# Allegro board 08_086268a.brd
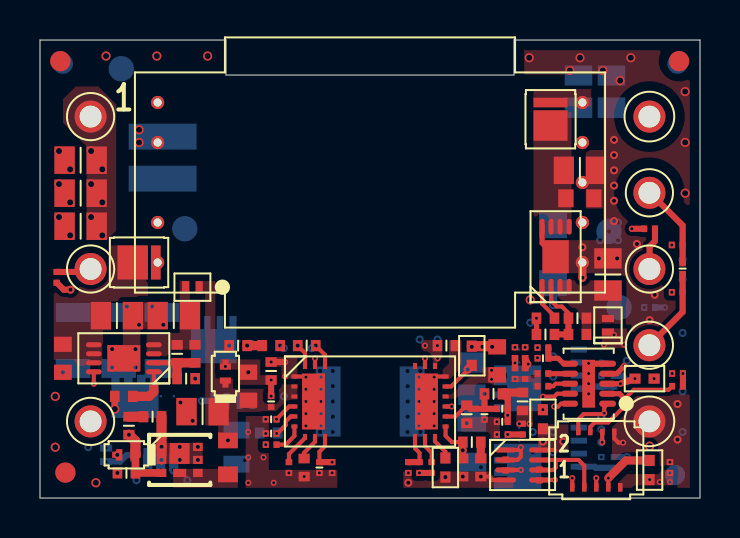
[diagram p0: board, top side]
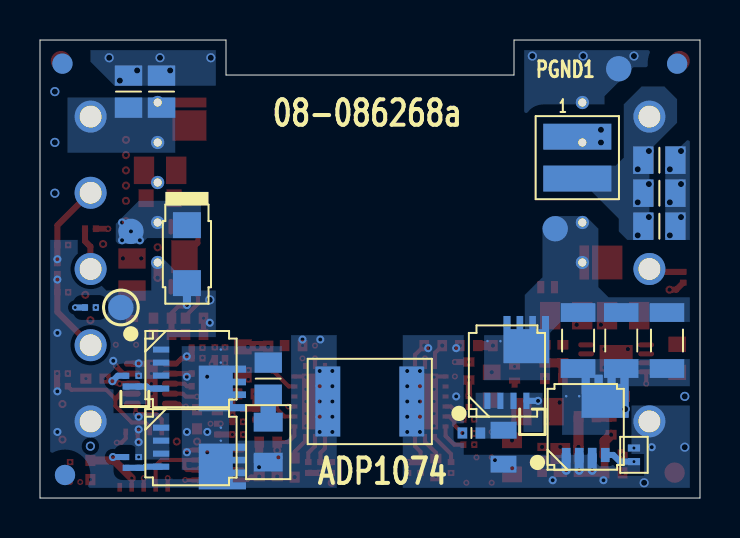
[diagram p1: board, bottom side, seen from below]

Outline 33 x 22.9 mm; copper layers: TOP, L2, L3, L4, L5, L6, L7, L8, L9, BOTTOM. Coordinates in mm from the lower left corner of the outline.
Outline path: 0,22.9 9.3,22.9 9.3,21.15 23.7,21.15 23.7,22.9 33,22.9 33,0 0,0 0,22.9

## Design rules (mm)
constraint set DEFAULT: min track width 0.305
net group DMAX: nets DMAX RT
net group ENABLE: nets ENABLE ON/OFFCONTROL
net group SR2: nets _N13 SR2
net group ASEL0: nets ALERT_N ASEL0 ASEL1 EN_I2C GP0 SCL SDA
net group COMP: nets _N50 COMP COMP_OUT
net group CS: nets CS
net group MODE: nets MODE PGOOD VREG2
net group PGATE: nets PGATE
net group PRI_AUX: nets _N29
net group SEC_AUX: nets _N31
net group SR_D: nets _N84
net group TRIM: nets _N4 FB FB_OUT IDAC OVP TRIM VSNS+ VSNS-

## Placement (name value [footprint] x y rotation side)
A1  ADA4075-2ACPZ  [DFN8_2X2]  24.13 1.65 270 top
C1  0.22UF  [C1206H71]  1.65 7.87 90 bottom
C2  0.22UF  [C1206H71]  3.94 7.87 90 bottom
C3  0.22UF  [C1206H71]  6.1 7.87 90 bottom
C4  2.2UF  [C0805H60]  26.92 20.32 90 bottom
C5  2.2UF  [C0805H60]  28.57 20.32 90 bottom
C6  2.2uF  [C0402H22]  30.23 5.97 180 top
C7  2.2uF  [C0402H22]  25.15 3.94 270 top
C8  2.2UF  [C0805H60]  2.03 15.24 180 bottom
C9  2.2UF  [C0805H60]  2.03 13.59 180 bottom
C10  2.2UF  [C0805H60]  8.13 4.32 180 top
C11  2.2UF  [C0805H60]  26.99 16.38 0 top
C12  1UF  [C0603]  26.99 14.99 0 top
C13  1UF  [C0603]  1.14 6.99 270 top
C14  2.2UF  [C0805H60]  3.85 9.12 0 top
C15  10NF  [C0402]  4.19 5.08 180 top
C16  10NF  [C0402]  25.27 8.99 180 top
C17  10UF  [C0805H55]  28.4 11.18 90 top
C18  2.2uF  [C0402H22]  30.48 1.4 90 top
C19  10UF  [C0805H55]  6.69 9.12 180 top
C20  2.2UF  [C0805H60]  2.03 15.24 180 top
C21  100NF  [C0402]  11.56 7.62 0 top
C22  1UF  [C0603]  22.86 6.86 270 top
C23  1UF  [C0603]  10.41 5.59 270 top
C24  0.015UF  [C0402]  13.21 1.52 270 top
C25  0.022uF  [C0402H22]  20.27 1.52 270 top
C26  0.033uF  [C0402]  22.04 1.52 270 top
C27  680pF  [C0402]  21.14 1.52 270 top
C28  2.2UF  [C0805H60]  2.03 13.59 180 top
C29  1000pF  [C0201]  13.97 1.52 270 top
C30  1000pF  [C0201]  11.56 3.94 180 top
C31  1000PF  [C0805H55]  21.59 5.97 270 bottom
C32  2.2uF  [C0402H22]  21.59 7.11 90 top
C34  0.1UF  [C0201]  11.56 4.83 90 top
C36  100PF  [C0201]  11.56 3.23 180 top
C39  10NF  [C0402]  26.87 8.18 0 top
C40  10NF  [C0402]  7.75 7.21 270 top
C41  100PF  [C0201]  23.11 3.81 180 top
C42  100PF  [C0201]  32.13 11.47 270 top
C45  2.2UF  [C0805H60]  2.03 16.89 180 bottom
C46  2.2UF  [C0805H60]  2.03 16.89 180 top
C47  100PF  [C0201]  22.23 4.19 270 top
C48  100PF  [C0201]  23.11 4.46 180 top
C49  2200pF  [C1812H63]  16.51 4.83 0 bottom
C63  100PF  [C0201]  25.15 6.99 180 top
D1  BZX884B11L-HG3-08  [DFN1006-2A]  9.27 6.22 90 top
D2  BZX884B11L-HG3-08  [DFN1006-2A]  4.32 2.16 180 top
D4  PMEG6010ESBYL  [DFN2_1X0_6]  3.3 2.16 270 bottom
D5  SDM1100LP-7  [DFN2020-2]  25.53 18.94 0 top
D6  V1F22-M3/H  [DO219AB]  25.65 12.19 270 bottom
D7  SDM1100LP-7  [DFN2020-2]  4.95 11.77 270 top
D13  PMEG6010ESBYL  [DFN2_1X0_6]  7.62 10.54 180 top
D15  PMEG6010ESBYL  [DFN2_1X0_6]  28.4 8.64 90 top
L1  1UH  [LSMSQ118H79_A]  6.13 17.02 90 bottom
NOREF  -  []  0 0 0 top
NOREF#2  -  []  -72.26 -74.17 0 top
NOREF#3  -  []  -228.6 -152.4 0 top
NOREF#4  -  [unnamed#2]  1.02 21.84 0 top
NOREF#5  -  []  -228.6 -152.4 0 top
NOREF#6  -  []  0 22.9 270 top
NOREF#7  -  []  325.12 314.96 0 top
NOREF#8  -  []  -228.6 -152.4 0 top
NOREF#9  -  []  0 0 0 top
NOREF#10  -  []  0 0 90 top
NOREF#11  -  [unnamed#2]  31.95 21.84 0 top
NOREF#12  -  []  0 0 0 top
NOREF#13  -  []  16.51 37.47 0 top
NOREF#14  -  []  33 0 90 top
NOREF#15  -  []  33 22.9 180 top
NOREF#16  -  [unnamed#2]  1.27 1.27 0 top
NOREF#17  -  [unnamed#2]  31.88 21.72 180 bottom
NOREF#18  -  [unnamed#2]  1.14 21.72 180 bottom
NOREF#19  -  [unnamed#2]  31.75 1.15 180 bottom
P1  5849-0-00-15-00-00-03-0  [CNMILMAX5849_AMH]  30.47 3.83 0 top
P2  3122-1-00-21-00-00-08-0  [CNMILLMAX3122-1]  2.53 19.07 0 top
P3  3122-1-00-21-00-00-08-0  [CNMILLMAX3122-1]  2.53 3.83 0 top
P4  3122-1-00-21-00-00-08-0  [CNMILLMAX3122-1]  2.53 11.45 0 top
P5  3122-1-00-21-00-00-08-0  [CNMILLMAX3122-1]  30.47 15.26 0 top
P6  3122-1-00-21-00-00-08-0  [CNMILLMAX3122-1]  30.47 11.45 0 top
P7  3122-1-00-21-00-00-08-0  [CNMILLMAX3122-1]  30.47 7.64 0 top
P8  5849-0-00-15-00-00-03-0  [CNMILMAX5849_AMH]  30.47 19.07 0 top
P10  AYF330935  [CNPANASONICAYF330935]  27.81 1.91 0 top
Q1  BSZ520N15NS3GATMA1  [TSDSON-8]  9.65 6.35 180 bottom
Q2  BSZ900N20NS3 G  [TSDSON-8]  25.45 6.45 270 bottom
Q3  BSZ900N20NS3 G  [TSDSON-8]  25.45 2.54 270 bottom
Q5  FDMC86259P  [POWER33]  5.71 3.56 180 bottom
Q6  FDMA86108LZ  [MLP6_2X2_PAD_9X1_PAD_2X_56]  6.99 1.91 270 top
R1  0  [R0201]  25.15 7.52 180 top
R2  0  [R0402]  20.32 7.62 180 top
R3  137K  [R0402]  22.68 5.21 180 top
R4  0  [R0201]  0.84 11.03 270 top
R5  2.8K  [R0402]  21.34 4.19 270 top
R6  220K  [R0402]  5.63 4.06 180 top
R7  220K  [R0402]  4.32 1.25 180 top
R8  220K  [R0402]  4.45 3.61 270 top
R9  0  [R0201]  23.28 1.65 90 top
R10  100  [R0603]  9.4 2.03 90 top
R11  2.05MEG  [R0402]  26.87 8.99 0 top
R12  124K  [R0402]  7.31 5.97 0 top
R13  0  [R0201]  24.26 7.26 90 top
R14  124K  [R0402]  25.27 8.18 180 top
R15  0  [R0201]  24.98 1.15 90 top
R17  10K  [R0402]  13.34 7.62 180 top
R18  4.7K  [R0402]  11.43 3.25 0 bottom
R20  3.74K  [R0402]  21.59 2.79 0 top
R21  0  [R0201]  28.7 5.84 90 bottom
R22  0  [R0402]  11.56 6.35 90 top
R23  0.005  [R0805]  9.82 2.54 270 bottom
R24  10K  [R0201]  28.07 5.84 90 bottom
R26  0  [R0201]  23.75 7.26 90 top
R27  0  [R0201]  12.45 1.52 270 top
R28  10K  [R0402]  9.91 7.62 180 top
R29  10  [R0805H20]  21.59 2.79 270 bottom
R30  0  [R0201]  18.41 1.52 270 top
R31  0  [R0201]  18.97 1.52 90 top
R32  8.2K  [R0201]  19.58 1.52 90 top
R37  20K  [R0201]  23.11 3.17 180 top
R38  2.05MEG  [R0402]  6.86 7.21 270 top
R39  10K  [R0201]  24.26 6.22 90 top
R40  10K  [R0201]  23.75 6.22 90 top
R41  0  [R0201]  31.86 12.65 0 top
R42  0  [R0201]  31.86 10.29 0 top
R43  0  [R0201]  30.48 13.46 180 top
R44  24K  [R0201]  11.56 2.67 0 top
R45  24K  [R0201]  14.61 1.52 270 top
R46  0  [R0201]  31.5 1.52 270 top
R48  0  [R0201]  28.7 1.78 90 bottom
R49  10K  [R0201]  28.07 1.78 90 bottom
R50  10  [R0402]  24.13 4.83 90 top
R51  1MEG  [R0201]  24.13 3.45 270 top
R64  10K  [R0201]  31.88 6.22 180 top
R65  10K  [R0201]  31.88 5.59 180 top
R66  10K  [R0201]  30.48 9.53 180 bottom
R69  10K  [R0201]  25.15 5.59 0 top
R70  10K  [R0201]  25.15 6.22 0 top
TP9  N/A  [TP_C127_P0]  28.96 9.53 180 bottom
TP10  N/A  [TP_C127_P0]  28.45 13.33 180 bottom
TP12  N/A  [TP_C127_P0]  7.24 13.46 180 bottom
TP16  N/A  [TP_C127_P0]  4.06 21.46 180 bottom
U4  EI14R1-0808-03-S03-20R-TH  [TTHL906W551H236]  5.88 19.77 0 top
U5  LT3062EDCB#PBF  [DFN8_2X3_PAD1_35X1_65_05-08-1718]  4.19 6.99 90 top
U6  LT3062EDCB#PBF  [DFN8_2X3_PAD1_35X1_65_05-08-1718]  25.78 12.06 0 top
U7  ADP1074ACCZ  [LGA24_4X8_2PAD2_8X1_15]  16.5 4.83 270 top
U9  LTC7106EDDB#PBF  [DFN10_3X2_PAD2_39X0_64]  27.43 5.71 90 top

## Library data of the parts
A1 = ADA4075_2: User Part Number: UPN; Tolerance: N/A; alternate symbols: (DFN8_2X2); tolerance: N/A
C1-C3 = CAP: Tolerance: 10; User Part Number: UPN; alternate symbols: (C1206H71L); tolerance: 10
C4 C5 C8-C11 C14 C17 C19 C20 C28 C45 C46 = CAP: User Part Number: UPN; Tolerance: 10; alternate symbols: (C0805L); tolerance: 10
C6 C7 C18 C32 = CAP: Tolerance: 20; User Part Number: UPN; alternate symbols: (C0402H22); tolerance: 20
C12 C13 C22 C23 = CAP: User Part Number: UPN; Tolerance: 10; alternate symbols: (C0603L); tolerance: 10
C15 C16 C21 C24 C26 C39 C40 = CAP: User Part Number: UPN; Tolerance: 10; alternate symbols: (C0402L); tolerance: 10
C25 = CAP: Tolerance: 10; User Part Number: UPN; alternate symbols: (C0402H22); tolerance: 10
C27 = CAP: User Part Number: UPN; Tolerance: 5; alternate symbols: (C0402L); tolerance: 5
C29 C30 = CAP: Tolerance: 10; User Part Number: UPN; alternate symbols: (C0201L); tolerance: 10
C31 = CAP: User Part Number: UPN; Tolerance: 5; alternate symbols: (C0805L); tolerance: 5
C34 = CAP: Tolerance: 20; User Part Number: UPN; alternate symbols: (C0201L); tolerance: 20
C36 C41 C42 C47 C48 C63 = CAP: Tolerance: 5; User Part Number: UPN; alternate symbols: (C0201L); tolerance: 5
C49 = CAP: Tolerance: 10; User Part Number: UPN; alternate symbols: (C1812H63); tolerance: 10
D1 D2 = DIOZNR: User Part Number: UPN; Tolerance: 2; alternate symbols: (DFN1006-2A); tolerance: 2
D4 D13 D15 = DIOSCHOTTKY: Tolerance: N/A; User Part Number: UPN; alternate symbols: (DFN2_1X0_6); tolerance: N/A
D5 D7 = DIOSCHOTTKY_V4: User Part Number: UPN; Tolerance: N/A; alternate symbols: (DFN2020-2); tolerance: N/A
D6 = DIOSCHOTTKY: User Part Number: UPN; Tolerance: N/A; alternate symbols: (DO219AB); tolerance: N/A
L1 = IND: User Part Number: UPN; Tolerance: 20; alternate symbols: (LSMSQ118H79_A); tolerance: 20
P1 P8 = CN1P: User Part Number: UPN; Tolerance: N/A; alternate symbols: (CNMILMAX5849_AMH); tolerance: N/A
P2-P7 = CN1P: User Part Number: UPN; Tolerance: N/A; alternate symbols: (CNMILLMAX3122-1); tolerance: N/A
P10 = CN9P: User Part Number: UPN; Tolerance: N/A; alternate symbols: (CNPANASONICAYF330935); tolerance: N/A
Q1 = TRANNMOSFET_V15: User Part Number: UPN; Tolerance: N/A; alternate symbols: (TSDSON-8); tolerance: N/A
Q2 Q3 = TRANNMOSFET8P: User Part Number: UPN; Tolerance: N/A; alternate symbols: (TSDSON-8); tolerance: N/A
Q5 = TRANPMOSFET_V9: Tolerance: N/A; User Part Number: UPN; alternate symbols: (POWER33); tolerance: N/A
Q6 = TRANNMOSFET_V31: Tolerance: N/A; User Part Number: UPN; alternate symbols: (MLP6_2X2_PAD_9X1_PAD_2X_56); tolerance: N/A
R1 R4 R9 R13 R15 R21 R26 R27 R30 R31 R41-R43 R46 R48 = RES: Tolerance: JUMPER; User Part Number: UPN; alternate symbols: (R0201L); tolerance: JUMPER
R2 R22 = RES: User Part Number: UPN; Tolerance: JUMPER; alternate symbols: (R0402L); tolerance: JUMPER
R3 = RES: User Part Number: UPN; Tolerance: 0.5; alternate symbols: (R0402L); tolerance: 0.5
R5 = RES: User Part Number: UPN; Tolerance: 0.1; alternate symbols: (R0402L); tolerance: 0.1
R6-R8 R11 R12 R14 R17 R18 R20 R28 R38 = RES: User Part Number: UPN; Tolerance: 1; alternate symbols: (R0402L); tolerance: 1
R10 = RES: User Part Number: UPN; Tolerance: 1; alternate symbols: (R0603); tolerance: 1
R23 = RES: User Part Number: UPN; Tolerance: 1; alternate symbols: (R0805L); tolerance: 1
R24 R39 R40 R49 R64-R66 R69 R70 = RES: Tolerance: 0.1; User Part Number: UPN; alternate symbols: (R0201L); tolerance: 0.1
R29 = RES: Tolerance: 0.1; User Part Number: UPN; alternate symbols: (R0805H20); tolerance: 0.1
R32 R44 R45 R51 = RES: Tolerance: 1; User Part Number: UPN; alternate symbols: (R0201L); tolerance: 1
R37 = RES: Tolerance: 5; User Part Number: UPN; alternate symbols: (R0201L); tolerance: 5
R50 = RES: User Part Number: UPN; Tolerance: 5; alternate symbols: (R0402L); tolerance: 5
TP9 TP10 TP12 TP16 = TP: alternate symbols: (TP_C127_P0)
U4 = XFMR9P_V4: User Part Number: UPN; Tolerance: N/A; alternate symbols: (TTHL906W551H236); tolerance: N/A
U5 U6 = ADLT3062: Tolerance: N/A; User Part Number: UPN; alternate symbols: (DFN8_2X3_PAD1_35X1_65_05-08-1718); tolerance: N/A
U7 = ADP1074: User Part Number: UPN; Tolerance: N/A; alternate symbols: (LGA24_4X8_2PAD2_8X1_15); tolerance: N/A
U9 = ADLTC7106_V2: User Part Number: UPN; Tolerance: N/A; alternate symbols: (DFN10_3X2_PAD2_39X0_64); tolerance: N/A

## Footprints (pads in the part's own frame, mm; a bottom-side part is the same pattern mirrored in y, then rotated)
C0201
  rect 0.305x0.33 smd: 1(-0.27,0) 2(0.27,0)
C0402
  rect 0.483x0.559 smd: 1(-0.45,0) 2(0.45,0)
C0402H22
  rect 0.559x0.508 smd: 1(-0.479,0) 2(0.479,0)
C0603
  rect 0.762x0.889 smd: 1(-0.7,0) 2(0.7,0)
C0805H55
  rect 1.016x1.372 smd: 1(-0.803,0) 2(0.803,0)
C0805H60
  rect 1.016x1.372 smd: 1(-0.803,0) 2(0.803,0)
C1206H71
  rect 0.94x1.727 smd: 1(-1.4,0) 2(1.4,0)
C1812H63
  rect 1.245x3.505 smd: 1(-2.1,0) 2(2.1,0)
CNMILLMAX3122-1
  round 1.6 hole 1.092: 1(0,0)
CNMILMAX5849_AMH
  round 1.6 hole 1.092: 1(0,0)
CNPANASONICAYF330935
  rect 0.229x0.432 smd: 1(-1.2,-1.369) 3(-0.6,-1.369) 5(0,-1.369) 7(0.6,-1.369) 9(1.2,-1.369)
  rect 0.229x0.33 smd: 2(-0.9,1.399) 4(-0.3,1.399) 6(0.3,1.399) 8(0.9,1.399)
DFN2_1X0_6
  rect 0.356x0.61 smd: A(0.34,0) C(-0.34,0)
DFN8_2X2
  oval 0.254x1.041 smd: 1(-0.75,-0.85) 2(-0.25,-0.85) 3(0.25,-0.85) 4(0.75,-0.85) 5(0.75,0.85) 6(0.25,0.85) 7(-0.25,0.85) 8(-0.75,0.85)
DFN8_2X3_PAD1_35X1_65_05-08-1718
  oval 0.254x0.787 smd: 1(-0.675,-1.5) 2(-0.225,-1.5) 3(0.225,-1.5) 4(0.675,-1.5) 5(0.675,1.5) 6(0.225,1.5) 7(-0.225,1.5) 8(-0.675,1.5)
  rect 1.321x1.651 smd: 9(0,0)
DFN10_3X2_PAD2_39X0_64
  oval 0.305x0.838 smd: 1(-1,-0.95) 2(-0.5,-0.95) 3(0,-0.95) 4(0.5,-0.95) 5(1,-0.95) 6(1,0.95) 7(0.5,0.95) 8(0,0.95) 9(-0.5,0.95) 10(-1,0.95)
  rect 2.388x0.635 smd: PAD(0,0)
DFN1006-2A
  custom 0.127x0.127 smd: A(0.454,0) C(-0.454,0)
DFN2020-2
  rect 1.702x1.524 smd: 1(0,-0.316)
  rect 1.702x0.483 smd: 2(0,0.837)
DO219AB
  rect 1.295x1.397 smd: A(1.45,0) C(-1.45,0)
LGA24_4X8_2PAD2_8X1_15
  rect 0.305x0.203 smd: 1(-1.775,-2.25) 2(-1.775,-2.75) 3(-1.775,-3.25) 10(1.775,-3.25) 11(1.775,-2.75) 12(1.775,-2.25) 13(1.775,2.25) 14(1.775,2.75) 15(1.775,3.25) 22(-1.775,3.25) 23(-1.775,2.75) 24(-1.775,2.25)
  rect 0.203x0.305 smd: 4(-1.25,-3.78) 5(-0.75,-3.78) 6(-0.25,-3.78) 7(0.25,-3.78) 8(0.75,-3.78) 9(1.25,-3.78) 16(1.25,3.78) 17(0.75,3.78) 18(0.25,3.78) 19(-0.25,3.78) 20(-0.75,3.78) 21(-1.25,3.78)
  rect 2.794x1.143 smd: PAD1(0,-2.825) PAD2(0,2.825)
LSMSQ118H79_A
  rect 1.295x3.404 smd: 1(-1.048,0) 2(1.048,0)
MLP6_2X2_PAD_9X1_PAD_2X_56
  rect 0.406x0.483 smd: 1(-0.65,-0.909) 2(0,-0.909) 3(0.65,-0.909) 4(0.65,0.909) 5(0,0.909) 6(-0.65,0.909)
  rect 1.041x0.991 smd: PAD1(-0.321,0)
  rect 0.406x0.66 smd: PAD2(0.653,0)
POWER33
  rect 0.432x0.711 smd: 1(-0.975,-1.404) 2(-0.325,-1.404) 3(0.325,-1.404) 4(0.975,-1.404)
  custom 0.54x0.54 smd: 5(0.97,1.531)
  round 0.127 smd: 6(0.325,1.535) 7(-0.325,1.535) 8(-0.975,1.535)
R0201
  rect 0.305x0.33 smd: 1(-0.27,0) 2(0.27,0)
R0402
  rect 0.483x0.559 smd: 1(-0.45,0) 2(0.45,0)
R0603
  rect 0.787x0.991 smd: 1(-0.85,0) 2(0.85,0)
R0805
  rect 0.838x1.295 smd: 1(-0.85,0) 2(0.85,0)
R0805H20
  rect 0.94x1.448 smd: 1(-1,0) 2(1,0)
TP_C127_P0
  round 1.27 smd: 1(0,0)
TSDSON-8
  rect 0.305x0.813 smd: 1(-0.975,-1.494) 2(-0.325,-1.494) 3(0.325,-1.494) 4(0.975,-1.494)
  custom 0.572x0.572 smd: 5(0.965,1.57)
  round 0.127 smd: 6(0.325,1.494) 7(-0.325,1.494) 8(-0.975,1.494)
TTHL906W551H236
  round 0.66 hole 0.406: 1(0,0) 2(0,-2) 4(0,-6) 5(0,-8) 6(21.238,-8) 7(21.238,-6) 8(21.238,-4) 9(21.238,-2) 10(21.238,0)
unnamed#2
  round 1.016 smd: (0,0)

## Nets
3V3_EXT: C6.2(N2) C18.2(N2) P10.7 R39.1 R40.1 R64.1 R65.1 R66.1 R69.1 R70.1 U9.3(VDD)
AGND1: C24.2(N2) C29.2(N2) C30.2(N2) C36.2(N2) R22.2(N2) R27.2(N2) R45.2(N2) U7.4 U7.PAD1
AGND2: A1.4(V-) C7.1 C25.2(N2) C26.2(N2) C27.2(N2) C41.2(N2) C47.2(N2) P10.1 R2.1 R5.2(N2) R30.2(N2) R37.2(N2) R42.1 U7.21 U7.PAD2
DGND: C6.1 C18.1 C63.2(N2) P10.9(N9) R13.2(N2) R26.2(N2) R46.2(N2) U9.5 U9.PAD
PGND1: C8.2(N2) C9.2(N2) C10.2(N2) C13.2(N2) C14.2(N2) C15.2(N2) C19.2(N2) C20.2(N2) C23.1 C28.2(N2) C34.2(N2) C45.2(N2) C46.2(N2) C49.1 D1.A(P) D2.A(P) D4.C P3.1(N1) Q5.1 Q5.2 Q5.3(S3) R12.2(N2) R17.2(N2) R22.1 R23.2(N2) R28.2(N2) TP16.1(TP1) U4.1 U5.8 U5.9 U7.3
PGND2: C4.2(N2) C5.2(N2) C11.2(N2) C12.2(N2) C16.2(N2) C17.2(N2) C22.1 C32.2(N2) C49.2(N2) D6.A(P) P1.1(N1) P10.8 Q2.1 Q2.2 Q2.3(S3) Q3.1 Q3.2 Q3.3(S3) R2.2(N2) R14.2(N2) R24.2(N2) R29.2(N2) R46.1 R49.2(N2) TP9.1(TP1) U4.6 U6.8 U6.9 U7.22
VIN+: C8.1 C9.1 C20.1 C28.1 C45.1 C46.1 L1.1 P2.1(N1) Q6.1 Q6.2 Q6.5 Q6.6 Q6.PAD1 R6.1
VIN_IC_1: C10.1 C23.2(N2) C34.1 D1.C D13.C R7.2(N2) R10.2(N2) U7.5 U7.6
VIN_IC_2: A1.8 C7.2(N2) C22.2(N2) D15.C U7.19
_N2: Q1.1 Q1.2 Q1.3(S3) R18.1 R23.1
_N3: C1.1 C2.1 C3.1 Q5.5 Q5.6 Q5.7 Q5.8
_N4: C41.1 C48.1 R3.1 R41.1 R50.2(N2)
_N8: R6.2(N2) R8.1
_N13: Q3.4 R48.1 R49.1
_N19: D2.C Q6.3 R7.1 R8.2(N2)
_N21: Q6.4 Q6.PAD2(S2) R10.1
_N27: C13.1 C14.1 D7.1(C) U5.5 U5.6 U5.7(SHDN_N)
_N29: C40.2(N2) R12.1 R38.2(N2) U5.2
_N31: C39.1 R11.1 R14.1 U6.2
_N33: C11.1 C12.1 D5.1(C) U6.5 U6.6 U6.7(SHDN_N)
_N36: C16.1 U6.1
_N37: C15.1 U5.1
_N50: C26.1 R20.2(N2)
_N52: Q2.4 R21.1 R24.1
_N59: C21.1 D4.A(P) Q5.4 R28.1
_N83: L1.2(N2) U4.2
_N84: C31.2(N2) R29.1
_N125: D5.2 U4.10
_N128: D7.2 U4.5
_N133: C1.2(N2) C2.2(N2) C3.2(N2) Q1.5 Q1.6 Q1.7 Q1.8 TP12.1(TP1) U4.4
ALERT_N: P10.6 R66.2(N2) U9.4
ASEL0: R26.1 R40.2(N2) U9.9
ASEL1: R13.1 R39.2(N2) U9.10
COMP: A1.3 C27.1 R9.1 R20.1 U7.16
COMP_OUT: A1.1 A1.2 P10.5 R9.2(N2)
CS: C36.1 R18.2(N2) U7.8
DMAX: C29.1 R44.1 R45.1 U7.12
EN_I2C: R70.2(N2) U9.7
ENABLE: C30.1 R4.2(N2) U7.7
FB: A1.5 C47.1 C48.2(N2) R1.2(N2) R3.2(N2) R5.1 R15.1 R43.2(N2) U7.17
FB_OUT: A1.6 A1.7 P10.3 R15.2(N2)
GP0: R69.2(N2) U9.8
IDAC: C63.1 R1.1 U9.6
MODE: R30.1 R31.2(N2) U7.13
NGATE: Q1.4 R17.1 U7.1
ON/OFFCONTROL: P4.1(N1) R4.1
OVP: R37.1 R51.2(N2) U7.18
PGATE: C21.2(N2) U7.2
PGOOD: R32.2(N2) U7.14
PRI_AUX: C19.1 C40.1 D13.A(P) R38.1 U5.3 U5.4
RT: R44.2(N2) U7.9
SCL: P10.4 R65.2(N2) U9.2
SDA: P10.2 R64.2(N2) U9.1
SEC_AUX: C17.1 C39.2(N2) D15.A(P) R11.2(N2) U6.3 U6.4
SR1: U7.24
SR2: R21.2(N2) R48.2(N2) U7.23
SR_D: C31.1 D6.C Q2.5 Q2.6 Q2.7 Q2.8 Q3.5 Q3.6 Q3.7 Q3.8 TP10.1(TP1) U4.7 U4.8(NC)
SS1: C24.1 U7.11
SS2: C25.1 U7.15
SYNC: R27.1 U7.10
TRIM: P6.1(N1) R43.1
VOUT: C4.1 C5.1 P8.1(N1) R50.1 R51.1 U4.9
VREG2: C32.1 R31.1 R32.1 U7.20(VREG2)
VSNS+: C42.1 P5.1(N1) R41.2(N2)
VSNS-: C42.2(N2) P7.1(N1) R42.2(N2)

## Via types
v1: diameter 0.305, hole 0.152, TOP to L2, 100 vias
v2: diameter 0.305, hole 0.152, L2 to L3, 97 vias
v3: diameter 0.762, hole 0.406, L3 to L8, 13 vias
v4: diameter 0.457, hole 0.305, L3 to L8, 39 vias
v5: diameter 0.406, hole 0.203, L8 to L9, 63 vias
v6: diameter 0.305, hole 0.152, L9 to BOTTOM, 6 vias
v7: diameter 0.305, hole 0.152, L4 to L5, 3 vias
v8: diameter 0.305, hole 0.152, L8 to L9, 9 vias
v9: diameter 0.406, hole 0.203, L9 to BOTTOM, 62 vias
v10: diameter 0.457, hole 0.305, TOP to BOTTOM, 32 vias
v11: diameter 0.66, hole 0.406, L2 to L3, 2 vias
v12: diameter 0.66, hole 0.406, L3 to L8, 6 vias
v13: diameter 0.457, hole 0.305, L6 to L7, 1 via
v14: diameter 0.66, hole 0.406, L8 to L9, 1 via
v15: diameter 0.406, hole 0.203, TOP to L2, 57 vias
v16: diameter 0.406, hole 0.203, L2 to L3, 50 vias
v17: diameter 0.305, hole 0.152, L6 to L7, 3 vias
v18: diameter 0.457, hole 0.305, L2 to L3, 1 via

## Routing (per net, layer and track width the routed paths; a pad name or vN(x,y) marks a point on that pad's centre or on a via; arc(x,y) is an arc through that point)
3V3_EXT: length 35.2
  TOP w0.203: P10.7 v2(28.41,0.99)
  TOP w0.254: U9.3 v2(29.02,5.71)
  TOP w0.305: R65.1 v2(32.15,6.22) ; v2(29.02,5.71) v2(29.75,5.97)
  TOP w0.406: C18.2 29.3,1.88 v2(28.41,0.99)
  L3 w0.305: v3(31.75,6.99) 32.15,6.59 v2(32.15,6.22) ; v2(23.75,5.95) v4(23.38,5.95)
  L3 w0.406: v3(28.82,0.99) v2(28.41,0.99) ; v3(31.75,6.99) 31.58,6.99 30.96,6.36 30.14,6.36 v2(29.75,5.97) v2(29.02,5.71)
  L6 w0.406: v4(23.38,5.95) 21.97,4.54 21.97,3.3 22.48,2.79 24.51,2.79 25.65,3.94 27.94,3.94 29.33,2.55 29.33,1.5 v3(28.82,0.99) 30.2,0.99 32.29,3.08 32.29,5.05 31.75,5.59 v3(31.75,6.99) 31.75,8.23 31.62,8.36 v3(31.62,9.14)
  L8 w0.406: v3(31.62,9.14) v6(31.24,9.53)
  BOTTOM w0.305: R66.1 v6(31.24,9.53)
AGND1: length 1.3
  TOP w0.203: U7.4 13.26,6.08 v2(13.29,6.05)
  TOP w0.305: v2(12.26,6.8) v2(11.56,6.8)
  vias: v1(10.41,3.3) v1(10.41,2.03) v1(10.41,0.76) v1(11.18,2.03) v1(11.29,3.94) v1(11.29,3.23) v1(11.68,0.76) v1(12.26,6.08) v1(12.45,1.25) v1(13.21,1.07) v1(13.29,5.44) v1(13.29,4.83) v1(13.29,4.22) v1(13.29,3.61) v1(13.97,1.25) v1(14.06,6.05) v1(14.06,5.44) v1(14.06,4.83) v1(14.06,4.22) v1(14.06,3.61) v1(14.61,1.25) v2(10.41,3.3) v2(10.41,2.03) v2(10.41,0.76) v2(11.18,2.03) v2(11.29,3.23) v2(11.68,0.76) v2(12.26,6.08) v2(12.45,1.25) v2(13.21,1.07) v2(13.29,5.44) v2(13.29,4.83) v2(13.29,4.22) v2(13.29,3.61) v2(13.97,1.25) v2(14.06,6.05) v2(14.06,5.44) v2(14.06,4.83) v2(14.06,4.22) v2(14.06,3.61) v2(14.61,1.25)
AGND2: length 14.9
  TOP w0.203: v1(19.71,6.05) 19.74,6.08 U7.21 ; v16(22.04,1.07) 22.45,1.07 22.62,0.9 A1.4 ; P10.1 v2(26.61,0.99)
  L3 w0.305: v2(31.59,10.29) v4(31.95,10.29)
  L6 w0.305: v4(31.95,10.29) 31.14,9.73 29.41,9.73 24.13,4.45 24.13,3.94 23.7,3.51 v4(22.84,3.51)
  vias: v1(18.41,1.25) v1(18.94,6.05) v1(18.94,5.44) v1(18.94,4.83) v1(18.94,4.22) v1(18.94,3.61) v1(19.71,5.44) v1(19.71,4.83) v1(19.71,4.22) v1(19.71,3.61) v1(22.23,3.92) v1(22.84,3.81) v1(22.84,3.17) v1(25.15,4.42) v2(18.94,6.05) v2(18.94,5.44) v2(18.94,4.83) v2(18.94,4.22) v2(18.94,3.61) v2(22.23,3.92) v2(22.84,3.81) v2(25.15,4.42) v15(18.41,0.76) v15(20.27,1.04) v15(21.14,1.07) v15(21.34,3.74) v16(18.41,0.76) v16(20.27,1.04) v16(21.14,1.07) v16(21.34,3.74)
DGND: length 2
  TOP w0.305: U9.5 27.43,6.71 v2(27.43,6.22) v2(27.43,5.71)
  vias: v1(23.75,7.53) v1(24.26,7.53) v1(24.88,7.01) v1(27.43,6.73) v1(27.43,5.21) v1(30.48,0.92) v1(30.71,5.97) v1(30.99,0.8) v1(31.5,1.25) v1(31.5,0.8) v2(23.75,7.53) v2(24.26,7.53) v2(24.88,7.01) v2(27.43,6.73) v2(27.43,5.21) v2(30.48,0.92) v2(30.99,0.8) v2(31.5,1.25) v2(31.5,0.8) v10(30.48,2.59)
PGND1: length 19.7
  TOP w0.203: U5.8 v2(2.69,5.71) ; U7.3 13.25,7.26 v16(12.88,7.62)
  TOP w0.305: C15.2 v10(3.74,4.45) ; v2(11.56,5.1) v2(11.56,5.9)
  L2 w0.762: v18(5.52,16.75) 4.2,16.75
  L2 w1.016: U4.1 4.57,19.77
  L3 w0.457: v18(5.52,16.75) v12(4.86,16.75)
  L3 w0.762: 4.45,20.32 4.99,19.77 U4.1
  L4 w1.016: U4.1 4.48,19.77
  L5 w1.016: U4.1 4.61,19.77
  L6 w0.66: v12(4.86,16.75) 5.46,16.75 ; U4.1 4.27,19.77
  L7 w0.66: U4.1 4.36,19.77
  L8 w1.016: U4.1 4.48,19.77
  L9 w0.66: U4.1 4.48,19.77
  BOTTOM w0.457: Q5.3 v9(5.39,1.39) ; Q5.2 v9(6.04,1.39) ; Q5.1 v9(6.69,1.39)
  vias: v1(9.27,6.58) v2(9.27,6.58) v2(10.41,6.29) v3(1.02,21.59) v4(0.76,0.89) v4(0.89,7.87) v4(1.61,9.14) v4(3.17,9.91) v4(4.19,6.99) v4(4.57,15.88) v4(4.57,13.21) v4(5.08,5.71) v4(5.08,3.81) v4(8.51,9.53) v4(8.76,2.41) v4(9.65,1.27) v4(11.56,5.5) v4(12.9,8.17) v4(14.27,0.74) v4(14.64,5.97) v4(14.64,4.45) v4(14.64,2.92) v5(2.41,2.54) v5(4.83,0.89) v5(7.37,0.89) v5(9.39,1.49) v5(10.25,1.89) v5(12.19,7.49) v5(12.19,5.08) v5(13.59,7.49) v5(14,6.35) v5(14,5.59) v5(14,4.83) v5(14,4.06) v5(14,3.3) v5(14.64,6.35) v5(14.64,5.59) v5(14.64,4.83) v5(14.64,4.06) v5(14.64,3.3) v6(3.3,2.5) v8(3.3,2.5) v9(2.41,2.54) v9(4.83,0.89) v9(7.37,0.89) v9(9.39,1.49) v9(10.25,1.89) v9(12.19,7.49) v9(12.19,5.08) v9(13.59,7.49) v9(14,6.35) v9(14,5.59) v9(14,4.83) v9(14,4.06) v9(14,3.3) v9(14.64,6.35) v9(14.64,5.59) v9(14.64,4.83) v9(14.64,4.06) v9(14.64,3.3) v10(0.76,5.08) v10(0.76,2.54) v10(0.95,17.35) v10(0.95,15.7) v10(0.95,14.05) v10(1.51,16.43) v10(1.51,14.78) v10(1.51,13.13) v10(2.79,0.76) v10(3.3,22.1) v10(5.84,22.1) v10(8.38,22.1) v15(1.14,6.29) v15(3.61,7.44) v15(3.61,6.53) v15(3.86,2.16) v15(4.34,9.58) v15(4.78,7.44) v15(4.78,6.53) v15(4.95,8.66) v15(5.61,9.58) v15(6.17,8.66) v15(7.02,4.78) v15(7.63,3.86) v15(7.76,5.97) v15(9.46,7.62) v15(10.41,6.29) v16(1.14,6.29) v16(3.61,7.44) v16(3.61,6.53) v16(3.86,2.16) v16(4.78,7.44) v16(4.78,6.53) v16(5.61,9.58) v16(6.17,8.66) v16(7.02,4.78) v16(7.63,3.86) v16(9.46,7.62)
PGND2: length 22.3
  TOP w0.203: v2(29.16,2.77) 28.92,2.77 28.71,2.98 P10.8
  TOP w0.254: R14.2 v2(24.82,8.99) ; U6.8 25.11,12.74 U6.9
  TOP w0.305: C32.2 v16(21.59,7.56)
  TOP w0.406: v15(27.12,11.01) U4.6
  TOP w0.508: C32.2 22.86,7.59 C22.1
  L2 w0.66: v2(28.85,11.98) v2(27.94,11.98) 27.74,11.77 U4.6
  L3 w0.406: v16(28.7,17.14) v16(28.7,16.38) v16(28.7,15.62) v16(28.7,14.86)
  L3 w0.66: v2(28.85,11.98) 28.85,11.77 U4.6
  L4 w0.66: v12(27.48,14.8) 28.52,14.8
  L4 w1.016: U4.6 28.41,11.77
  L6 w0.66: v12(27.48,14.8) 28.26,14.8
  L7 w0.66: U4.6 28.54,11.77
  L8 w0.406: v9(28.07,6.73) 28.45,6.35 ; 28.83,15.24 28.39,14.8 v12(27.48,14.8)
  L8 w0.66: 28.45,16.75 27.48,16.75
  L9 w0.66: U4.6 28.67,11.77
  BOTTOM w0.305: R29.2 v9(21.08,2.03)
  BOTTOM w0.406: D6.A v9(25.65,9.65)
  vias: v1(19.25,7.62) v1(19.87,7.62) v1(19.88,6.98) v1(31.5,1.79) v2(19.25,7.62) v2(19.87,7.62) v2(19.88,6.98) v2(31.5,1.79) v3(31.88,13.72) v4(18.54,8) v4(19.43,8) v4(20.32,8) v4(22.73,0.89) v4(28.45,1.78) v4(30.81,8.89) v4(31.5,4.7) v5(18.38,6.35) v5(18.38,5.59) v5(18.38,4.83) v5(18.38,4.06) v5(18.38,3.3) v5(18.99,7.92) v5(19.02,6.35) v5(19.02,5.59) v5(19.02,4.83) v5(19.02,4.06) v5(19.02,3.3) v5(19.88,7.92) v5(24.51,8.76) v5(28.07,4.06) v5(28.07,3.43) v5(28.07,2.79) v5(29.34,6.86) v5(32.13,11.94) v5(32.13,10.92) v5(32.13,8.26) v5(32.13,5.33) v5(32.13,3.3) v6(28.07,6.11) v6(28.07,2.05) v8(22.05,1.54) v8(28.07,6.11) v8(28.07,2.05) v9(18.38,6.35) v9(18.38,5.59) v9(18.38,4.83) v9(18.38,4.06) v9(18.38,3.3) v9(18.99,7.92) v9(19.02,6.35) v9(19.02,5.59) v9(19.02,4.83) v9(19.02,4.06) v9(19.02,3.3) v9(19.88,7.92) v9(22.05,1.54) v9(24.51,8.76) v9(28.07,4.06) v9(28.07,3.43) v9(28.07,2.79) v9(29.34,6.86) v9(32.13,11.94) v9(32.13,10.92) v9(32.13,8.26) v9(32.13,5.33) v9(32.13,3.3) v10(24.46,22.01) v10(24.51,9.91) v10(26.49,21.38) v10(27,22.01) v10(28.14,21.38) v10(29.01,20.87) v10(29.54,22.01) v10(32.26,20.32) v10(32.26,17.78) v10(32.26,15.24) v15(22.12,7.56) v15(22.61,7.56) v15(27.12,12.54) v15(28.7,17.91) v15(28.7,13.84) v15(29.84,12.7) v15(30.48,8.89) v15(30.73,10.16) v15(31.88,4.7) v15(31.88,2.92) v16(22.12,7.56) v16(22.61,7.56) v16(28.7,17.91) v16(28.7,13.84) v16(29.84,12.7) v16(30.48,8.89) v16(30.73,10.16) v16(31.88,4.7) v16(31.88,2.92)
VIN+: length 13.9
  TOP w0.457: 6.08,2.16 v16(6.08,1.91)
  TOP w0.508: R6.1 v16(6.08,2.56) 6.08,2.16
  L3 w0.508: 3.14,13.11 4.19,12.06 4.19,9.14 6.08,7.26 v16(6.08,2.56)
  vias: v10(2.56,17.35) v10(2.56,15.7) v10(2.56,14.05) v10(3.11,16.43) v10(3.11,14.78) v10(3.11,13.13) v15(6.99,2.56) v15(6.99,1.91) v15(7.89,2.56) v15(7.89,1.91) v16(6.99,2.56) v16(6.99,1.91) v16(7.89,2.56) v16(7.89,1.91)
VIN_IC_1: length 7
  L3 w0.406: v16(9.4,2.88) 9.4,2.03 8.26,0.89 4.24,0.89 v16(3.87,1.25)
VIN_IC_2: length 21
  TOP w0.203: A1.8 25.74,2.4
  L3 w0.305: v2(29.21,7.66) v3(28.7,7.66) ; v3(28.7,7.66) v2(28.7,8.15) ; v3(28.7,7.66) v2(28.19,7.66)
  L3 w0.508: v3(27.18,2.82) v16(26.16,2.82) v16(25.15,2.82)
  L5 w0.508: v3(28.7,7.66) 28.7,5.84 27.18,4.32 v3(27.18,2.82)
  L6 w0.508: v3(27.18,2.82) 26.13,1.78 22.23,1.78 21.08,2.92 21.08,4.75 22.22,5.89 v3(22.22,6.72)
  vias: v1(22.58,6.39) v1(22.58,5.93) v2(22.58,6.39) v2(22.58,5.93)
_N4: length 16.6
  TOP w0.305: 23.38,4.95 23.38,5.21 R3.1 23.38,4.95 ; 23.38,4.95 v4(23.38,4.46) v2(23.38,4.14) C41.1
  TOP w0.406: R50.2 23.19,5.28 R3.1
  L3 w0.305: v2(23.38,4.14) v4(23.38,4.46) ; v2(31.59,12.65) v4(31.95,12.65)
  L6 w0.305: v4(31.95,12.65) 31.95,11.18 31.06,10.29 29.21,10.29 v4(23.38,4.46)
_N8: length 0.7
  TOP w0.508: R6.2 R8.1
_N13: length 1.8
  BOTTOM w0.305: Q3.4 27.73,1.56 27.79,1.51 R49.1 R48.1
_N19: length 3.3
  TOP w0.381: D2.C R7.1 Q6.3
  TOP w0.508: D2.C 4.77,2.84 v16(4.45,3.16)
_N29: length 2.8
  TOP w0.254: U5.2 R38.2
  TOP w0.457: C40.2 R38.2 R12.1
_N31: length 3.6
  TOP w0.203: R11.1 26.42,9.24 26.09,9.58 25.84,9.58 25.56,9.86 U6.2
  TOP w0.305: R11.1 C39.1 R14.1
_N36: length 1.8
  TOP w0.203: U6.1 25.11,9.71 25.72,9.09 C16.1
_N37: length 2.1
  TOP w0.203: 5.69,5.61 U5.1
  TOP w0.457: C15.1 5.46,5.08 5.69,5.31 5.69,5.61
_N50: length 0.8
  TOP w0.406: R20.2 C26.1
_N52: length 1.8
  BOTTOM w0.305: Q2.4 27.57,5.47 27.67,5.57 R24.1 R21.1
_N59: length 13.6
  TOP w0.457: C21.1 v16(10.36,7.62)
  L3 w0.254: v4(8.79,7.6) 8.79,7.54 9.24,7.09 9.82,7.09 v16(10.36,7.62)
  L6 w0.305: v4(3.01,1.82) 4.36,1.82 6.12,3.58 6.12,4.93 v4(8.79,7.6)
  L8 w0.305: v6(3.3,1.82) v4(3.01,1.82)
  BOTTOM w0.305: v6(3.3,1.82) 4,1.82 4.34,2.15 Q5.4
_N83: length 2.2
  L2 w0.406: U4.2 v10(4.95,17.77) v10(4.95,18.41) 5.47,18.41 5.59,18.29
  vias: v2(8.72,17.11) v2(8.72,16.66) v2(8.72,16.21) v12(5.88,15.78) v17(8.72,15.34) v17(8.72,14.89) v17(8.72,14.44)
_N84: length 1.4
  BOTTOM w0.762: C31.2 R29.1
_N125: length 1.3
  L3 w0.66: v14(27.12,19.77) v12(27.78,19.77)
  L8 w0.66: v12(27.78,19.77) v14(27.12,19.77)
  vias: v5(27.48,16.75)
_N128: length 0.4
  L3 w0.66: v11(5.88,11.77) v12(5.46,11.77)
  vias: v13(5.52,14.8)
ALERT_N: length 12
  TOP w0.203: P10.6 v2(28.11,2.78)
  TOP w0.254: v2(29.21,6.6) 29.13,6.53 29.13,6.52 28.85,6.23 28.84,6.23 28.82,6.21 U9.4
  L3 w0.305: 28.28,6.6 27.53,7.35 27.53,8.28 28.02,8.76 29.41,8.76 29.72,9.07 v4(29.72,9.14) ; 28.28,6.6 v2(29.21,6.6) ; 28.28,6.6 28.28,5.29 27.6,4.61 27.6,4.02 28.11,3.51 v2(28.11,2.78)
  L8 w0.406: v6(30.21,9.53) v4(29.72,9.14)
ASEL0: length 4.1
  TOP w0.203: v2(25.15,5.07) 25.71,5.07 25.86,5.22 U9.9
  TOP w0.305: R26.1 v2(23.75,6.75) R40.2
  L3 w0.254: v2(23.75,6.75) 23.93,6.49 24.46,5.96 v2(25.15,5.07)
ASEL1: length 4.6
  TOP w0.203: U9.10 26.05,4.72 25.91,4.57 v2(25.71,4.57)
  TOP w0.305: R39.2 v2(24.41,6.69) R13.1 R39.2
  L3 w0.254: v2(25.71,4.57) 25.71,5.4 v2(24.41,6.69)
COMP: length 6.3
  TOP w0.203: U7.16 20.28,3.11 20.59,2.79 R20.1 ; A1.3 v2(24.04,1.4)
  TOP w0.305: R20.1 v16(21.14,2.38) C27.1
  L3 w0.305: v16(21.14,2.38) 21.7,2.38 21.92,2.16 23.28,2.16 v2(24.04,1.4)
COMP_OUT: length 7
  TOP w0.203: P10.5 v2(27.81,0.99) ; A1.2 23.87,1.9 24.04,2.07 v2(24.04,2.53) 23.91,2.4 A1.1
  L3 w0.305: v2(27.81,0.99) 27.45,1.35 26.97,1.35 26.82,1.5 26.82,1.5 26.42,1.91 24.66,1.91 v2(24.04,2.53)
CS: length 2.3
  TOP w0.203: U7.8 12.53,4.08 12.28,3.83 12.28,3.65 11.86,3.23 v2(11.83,3.23)
  L3 w0.356: v2(11.83,3.23) v3(12.18,2.91)
  L8 w0.508: v9(11.88,3.25) v3(12.18,2.91)
DMAX: length 5.7
  TOP w0.203: C29.1 13.97,2.31 14.25,2.59 U7.12
  TOP w0.305: C29.1 v2(14.61,1.79)
  L3 w0.305: v2(14.61,1.79) 12.16,1.79 v2(11.29,2.67)
EN_I2C: length 1.1
  TOP w0.254: U9.7 25.42,6.21
  TOP w0.305: 25.42,6.21 R70.2
ENABLE: length 18.8
  TOP w0.203: v2(11.83,3.94) 11.83,3.94 12.46,4.58 U7.7
  TOP w0.305: v2(1.52,10.41) 1.19,10.41 R4.2
  L3 w0.305: v3(1.84,5.4) 1.84,6.16 2.54,6.86 2.54,9.4 v2(1.52,10.41) ; v3(10.79,3.94) v2(11.83,3.94)
  L5 w0.305: v3(1.84,5.4) 4.39,5.4 6.49,3.3 10.16,3.3 v3(10.79,3.94)
FB: length 35.3
  TOP w0.203: R5.1 20.77,4.08 U7.17 ; A1.5 v2(25.74,0.9)
  TOP w0.305: v16(22.23,5.21) C47.1 ; C47.1 21.52,4.46 R5.1 ; C47.1 C48.2 ; R43.2 v2(29.59,13.46)
  L3 w0.305: v2(29.59,13.46) v4(30.99,13.46) ; v2(25.74,0.9) 24.14,0.9 24.13,0.89 23.62,0.89 22.86,1.65 20.57,1.65 19.68,2.54 19.68,5.21 ; v16(22.23,5.21) 19.68,5.21 ; 19.68,5.21 19.68,5.97 20.57,6.86 20.57,7.33 21.36,8.12 24.54,8.12 v4(24.62,8.04) 24.64,8.02 24.64,8 24.88,7.76 v2(24.88,7.52)
  L6 w0.305: v4(30.99,13.46) 30.1,13.46 29.21,12.57 29.21,11.18 26.08,8.04 v4(24.62,8.04)
FB_OUT: length 4.7
  TOP w0.203: 25.78,1.9 25.78,1.52 25.65,1.4 24.98,1.4 A1.6 ; 25.78,1.9 A1.7 ; 25.78,1.9 26.93,1.9 27.21,1.62 P10.3
GP0: length 1.1
  TOP w0.203: U9.8 25.78,5.71 25.65,5.59 R69.2
IDAC: length 1.7
  TOP w0.254: U9.6 26.18,6.71 25.91,6.99 C63.1
  TOP w0.305: R1.1 C63.1
MODE: length 1.9
  TOP w0.203: R31.2 18.97,2.26 18.75,2.48 U7.13
  TOP w0.305: R31.2 R30.1
NGATE: length 10.5
  TOP w0.203: U7.1 14.25,7.16 v16(13.79,7.62)
  L3 w0.406: v16(13.79,7.62) v4(14.35,7.62)
  L6 w0.305: v12(7.82,4.58) 9.97,6.73 13.46,6.73 v4(14.35,7.62)
  L8 w0.406: v9(8.1,4.86) v12(7.82,4.58)
  BOTTOM w0.305: Q1.4 v9(8.1,4.86)
ON/OFFCONTROL: length 1.8
  TOP w0.305: 2.38,11.3 2.41,11.3 ; 2.38,11.3 0.84,11.3 ; 2.38,11.3 P4.1
OVP: length 5.8
  TOP w0.203: v16(20.28,4.58) v1(20.58,4.58)
  TOP w0.305: R51.2 v2(23.38,3.17)
  L2 w0.305: v1(20.58,4.58) v16(20.28,4.58)
  L3 w0.305: v16(20.28,4.58) 20.28,3.72 20.83,3.17 21.72,3.17 22.08,2.82 23.02,2.82 v2(23.38,3.17)
PGATE: length 2.4
  TOP w0.203: U7.2 v2(13.75,6.98)
  L3 w0.254: v2(13.75,6.98) 12.76,6.98 12.47,7.27 v16(12.01,7.62)
PGOOD: length 1.4
  TOP w0.203: R32.2 19.58,2.26 19.25,2.59 U7.14
RT: length 1.5
  TOP w0.203: U7.9 12.72,3.1 12.28,2.67 R44.2
SCL: length 6.4
  TOP w0.203: R65.2 31.43,5.41 29.69,5.41 29.23,4.95 29.23,4.59 28.41,3.77 27.73,3.77 27.51,3.56 P10.4
  TOP w0.254: 29.23,4.95 29.23,4.96 28.98,5.22 U9.2
SDA: length 7
  TOP w0.203: U9.1 28.21,4.55 28.21,4.24 v2(28.2,4.23) 28.16,4.19 27.18,4.19 26.91,3.93 P10.2
  L3 w0.305: v2(31.61,6.22) 31.61,5.92 31.09,5.4 30.38,5.4 28.45,4.73 28.2,4.38 v2(28.2,4.23)
SR2: length 22.1
  TOP w0.203: U7.23 v2(19.25,6.98)
  L3 w0.305: v2(19.25,6.98) v4(18.67,6.98)
  L5 w0.406: v4(28.84,4.08) 28,3.24 28,2.35 27.18,1.52 21.72,1.52 18.67,4.58 v4(18.67,6.98)
  L8 w0.406: v9(29.35,2.05) 28.84,2.56 v4(28.84,4.08) 29.38,4.62 v9(29.38,5.84)
  BOTTOM w0.305: R48.2 v9(29.35,2.05) ; v9(29.38,5.84) 29.11,6.11 R21.2
SR_D: length 3.4
  L8 w0.305: v9(28.01,12.89) v9(28.45,13.33) v9(28.9,13.78)
  L8 w0.66: U4.7 28.01,13.78 v9(28.45,13.33) v9(28.9,12.89)
  vias: v5(24.64,6.07) v5(24.64,3.3) v5(24.64,2.29) v5(25.66,7.08) v5(25.66,6.07) v5(25.65,3.3) v5(25.65,2.29) v7(24.28,15.34) v7(24.28,14.89) v7(24.28,14.44) v8(24.28,17.11) v8(24.28,16.66) v8(24.28,16.21) v9(24.64,6.07) v9(24.64,3.3) v9(24.64,2.29) v9(25.66,7.08) v9(25.66,6.07) v9(25.65,3.3) v9(25.65,2.29)
SS1: length 1.3
  TOP w0.203: C24.1 13.21,2.27 13.75,2.81 U7.11
SS2: length 1.3
  TOP w0.203: U7.15 19.75,2.83 20.27,2.31 C25.1
SYNC: length 1.6
  TOP w0.203: R27.1 12.45,2.2 13.25,3 U7.10
TRIM: length 2.1
  TOP w0.305: R43.1 30.75,12.84 30.48,12.57 30.48,11.46 P6.1
VOUT: length 18.5
  L3 w0.457: v4(26.8,5.71) 26.8,4.32 26.19,3.72 v2(24.47,3.72) v2(23.96,3.72)
  L5 w0.457: v4(26.8,5.71) 26.8,8.89 28.57,10.67 28.57,17.4 28.2,17.77 U4.9
VREG2: length 8.8
  TOP w0.203: U7.20 20.56,5.58 21.59,6.61 C32.1
  TOP w0.305: v2(18.97,1.25) R32.1
  TOP w0.406: v16(21.39,6.43) C32.1
  L3 w0.406: v16(21.39,6.43) v3(20.95,6) ; v2(18.97,1.25) v3(18.97,1.91)
  L8 w0.406: v3(20.95,6) 20.19,5.24 20.19,3.12 v3(18.97,1.91)
VSNS+: length 4.2
  TOP w0.305: P5.1 30.5,15.26 32.13,13.63 R41.2 C42.1
VSNS-: length 4.2
  TOP w0.305: P7.1 32.13,9.3 R42.2 C42.2

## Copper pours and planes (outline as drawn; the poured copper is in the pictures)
3V3_EXT on TOP: 25.03,6.39 25.03,5.42 24.64,5.42 24.64,5.8 23.58,5.8 23.58,6.11 24.64,6.11 24.64,6.39
AGND1 on TOP: 12.87,5.97 12.06,5.97 12.06,6.56 11.28,6.56 11.28,7.04 12.87,7.04
AGND1 on TOP: 10.29,4.1 11.44,4.1 11.44,1.41 14.86,1.41 14.86,0.51 10.29,0.51
AGND1 on L2, L3: 11.2,6.96 14.86,6.96 14.86,0.51 10.19,0.51 10.19,4.55 11.94,4.55 12.05,4.59 12.09,4.7 12.09,6.35 12.05,6.46 11.94,6.5 11.2,6.5
AGND2 on TOP: 18.16,1.32 23.67,1.32 23.67,0.51 18.16,0.51
AGND2 on TOP: 20.13,5.97 20.71,5.97 21.08,6.35 21.08,7.87 20.45,7.87 20.45,6.73 20.13,6.41
AGND2 on TOP: 22.23,4.07 21.06,4.07 21.06,3.3 21.97,3.3 21.97,3.01 23,3.01 23,4.06 22.23,4.06
AGND2 on L2: 20.47,6.96 22.71,6.96 22.71,4.83 22.75,4.72 22.86,4.67 27.03,4.67 27.03,0.51 18.16,0.51 18.16,6.32 20.32,6.32 20.43,6.37 20.47,6.48
AGND2 on L3: 21.74,7.41 28.68,7.41 28.68,0.53 28.68,0.51 18.16,0.51 18.16,6.32 21.59,6.32 21.7,6.37 21.74,6.48
DGND on TOP: 31.66,1.41 31.12,1.41 30.91,1.2 29.34,1.2 28.9,0.75 28.9,0.51 29.59,0.51 29.72,0.64 31.66,0.64
DGND on L2: 23.01,7.72 32.49,7.72 32.49,0.51 27.33,0.51 27.33,4.83 27.29,4.93 27.18,4.98 23.01,4.98
PGND1 on L2 (solid shape): 25.93,20.68 26.2,20.57 26.31,20.3 26.31,11.25 26.2,10.98 25.93,10.87 6.82,10.87 6.56,10.98 6.44,11.25 6.44,15.78 6.28,16.17 5.88,16.34 5.52,16.34 5.12,16.78 5.6,17.13 5.68,17.1 5.71,17.09 5.75,17.06 6.46,17.06 6.71,16.97 6.84,16.73 6.84,11.84 6.84,11.78 6.87,11.67 6.92,11.56 6.99,11.46 7.08,11.38 7.19,11.32 7.3,11.28 7.41,11.27 25.34,11.27 25.4,11.27 25.51,11.29 25.62,11.34 25.72,11.42 25.8,11.51 25.86,11.61 25.9,11.73 25.91,11.84 25.91,19.71 25.91,19.77 25.89,19.88 25.84,19.99 25.76,20.09 25.67,20.17 25.57,20.23 25.45,20.27 25.34,20.28 7.06,20.28 7.01,20.28 6.86,20.28 6.59,20.17 6.48,19.9 6.48,19.77 6.47,19.7 6.45,19.59 6.4,19.49 6.34,19.4 6.27,19.33 6.18,19.26 6.09,19.22 5.99,19.19 5.87,19.18 5.82,19.18 5.44,19.37 5.28,19.77 5.28,20.3 5.39,20.57 5.66,20.68
PGND1 on L6 (solid shape): 26.09,20.57 26.2,20.3 26.2,11.25 26.09,10.98 25.82,10.87 6.82,10.87 6.56,10.98 6.44,11.25 6.44,13.79 6.28,14.19 5.88,14.35 5.52,14.35 5.14,14.87 5.75,15.08 6.46,15.08 6.73,14.96 6.84,14.69 6.84,11.85 7.01,11.44 7.42,11.27 25.22,11.27 25.63,11.44 25.8,11.85 25.8,19.7 25.63,20.11 25.22,20.28 7.42,20.28 7.01,20.11 6.84,19.7 6.84,17.76 6.66,17.2 6.18,16.85 6,16.75 5.86,16.59 5.17,16.6 5.52,17.2 5.88,17.2 6.28,17.36 6.44,17.76 6.44,20.3 6.56,20.57 6.82,20.68 25.82,20.68
PGND1 on TOP: 6.4,9.8 4.14,9.8 4.14,6.32 5.02,6.32 5.02,8.43 6.4,8.43
PGND1 on TOP: 11.84,5.66 9.97,5.66 9.97,6.42 8.99,6.42 8.99,6.93 11.01,6.93 11.01,6.14 11.84,6.14
PGND1 on BOTTOM: 11.81,8.38 14.86,8.38 14.86,0.51 0.51,0.51 0.51,4.62 3.43,4.62 3.43,2.16 11.81,2.16
PGND1 on BOTTOM: 1.74,17.58 1.74,12.9 0.72,12.9 0.72,17.58
PGND1 on BOTTOM: 0.51,22.39 8.79,22.39 8.79,12.9 0.51,12.9 ; 1 cut-out
PGND1 on L2, L3: 0.51,22.39 8.79,22.39 8.79,21.18 5,21.18 4.89,21.13 4.85,21.03 4.85,10.52 4.89,10.42 5,10.37 14.86,10.37 14.86,7.26 11.05,7.26 10.94,7.22 10.9,7.11 10.9,6.35 10.94,6.24 11.05,6.2 11.79,6.2 11.79,4.85 10.03,4.85 9.93,4.81 9.88,4.7 9.88,0.51 0.51,0.51
PGND1 on L4, L5, L6, L7, L8, L9: 0.51,22.39 8.79,22.39 8.79,21.18 5,21.18 4.89,21.13 4.85,21.03 4.85,10.52 4.89,10.42 5,10.37 14.86,10.37 14.86,0.51 0.51,0.51
PGND2 on L8 (solid shape): 26.44,20.57 26.56,20.3 26.56,17.76 26.72,17.36 27.12,17.2 27.48,17.2 27.86,16.68 27.25,16.47 26.54,16.47 26.27,16.59 26.16,16.86 26.16,19.7 25.99,20.11 25.58,20.28 7.78,20.28 7.37,20.11 7.2,19.7 7.2,11.85 7.37,11.44 7.78,11.27 25.58,11.27 25.99,11.44 26.16,11.85 26.16,13.79 26.34,14.35 26.82,14.7 27,14.8 27.14,14.96 27.83,14.95 27.48,14.35 27.12,14.35 26.72,14.19 26.56,13.79 26.56,11.25 26.44,10.98 26.18,10.87 7.18,10.87 6.91,10.98 6.8,11.25 6.8,20.3 6.91,20.57 7.18,20.68 26.18,20.68
PGND2 on TOP: 19.65,6.45 19.85,6.45 19.85,6.75 20.11,7.01 20.11,7.9 19.2,7.9 19.05,7.75 19.05,7.49 19.65,6.89
PGND2 on TOP: 24.21,22.39 32.49,22.39 32.49,14.5 31.88,15.11 31.62,15.11 31.37,14.86 31.37,13.97 31.75,13.59 32.38,13.59 32.49,13.7 32.49,0.51 18.16,0.51 18.16,10.37 28,10.37 28.11,10.42 28.15,10.52 28.15,21.03 28.11,21.13 28,21.18 24.21,21.18 ; 2 cut-outs
PGND2 on TOP: 25.12,11.24 29.08,11.24 29.08,12.89 25.12,12.89
PGND2 on TOP: 27.29,14.48 27.29,17.4 28.96,17.4 28.96,14.48
PGND2 on BOTTOM: 24.21,22.39 30.48,22.39 30.48,21.82 29.27,20.61 24.21,20.61
PGND2 on BOTTOM: 26.54,2.57 28.23,2.57 28.23,1.9 26.54,1.9
PGND2 on BOTTOM: 28.23,5.96 26.54,5.96 26.54,6.63 28.23,6.63
PGND2 on BOTTOM: 32.49,12.91 32.49,0.51 18.16,0.51 18.16,10.37 29.68,10.37 31.11,11.81 31.11,12.91 ; 3 cut-outs
PGND2 on BOTTOM: 26.8,11.94 26.8,11.93 26.26,11.39 24.96,11.39 24.96,10.09 27.24,10.09 27.43,10.29 27.43,11.81 27.18,12.06 26.92,12.06
PGND2 on L2: 24.21,22.39 32.49,22.39 32.49,8.03 22.86,8.03 22.75,7.98 22.71,7.87 22.71,7.26 20.32,7.26 20.21,7.22 20.17,7.11 20.17,6.63 18.16,6.63 18.16,10.37 28,10.37 28.11,10.42 28.15,10.52 28.15,21.03 28.11,21.13 28,21.18 24.21,21.18
PGND2 on L3: 24.21,22.39 32.49,22.39 32.49,7.71 21.59,7.71 21.48,7.67 21.44,7.56 21.44,6.63 18.16,6.63 18.16,10.37 28,10.37 28.11,10.42 28.15,10.52 28.15,21.03 28.11,21.13 28,21.18 24.21,21.18
PGND2 on L3: 28.98,7.41 32.49,7.41 32.49,0.51 28.98,0.51 28.98,0.53
PGND2 on L4, L5, L6, L7, L8: 24.21,22.39 32.49,22.39 32.49,0.51 18.16,0.51 18.16,10.37 28,10.37 28.11,10.42 28.15,10.52 28.15,21.03 28.11,21.13 28,21.18 24.21,21.18
PGND2 on L6: 27.09,9.74 28.45,11.1 28.45,12.19 28.32,12.32 28.17,12.32 27.96,12.11 27.12,12.11 26.79,11.77 26.8,11.77 26.8,10.56 26.54,10.31 26.54,10.03 26.83,9.74
PGND2 on L9: 24.21,22.39 32.49,22.39 32.49,0.51 18.16,0.51 18.16,10.37 28,10.37 28.11,10.42 28.15,10.52 28.15,12.31 28.9,12.31 29.3,12.48 29.47,12.88 29.47,13.79 29.47,13.79 29.29,14.18 28.9,14.35 28.15,14.35 28.15,21.03 28.11,21.13 28,21.18 24.21,21.18 ; 7 cut-outs
VIN+ on TOP: 8.14,1.7 5.83,1.7 5.83,2.76 8.14,2.76
VIN+ on TOP: 2.33,17.58 1.14,18.76 1.14,19.94 1.78,20.57 2.92,20.57 3.81,19.68 3.81,13.37 3.34,12.9 2.33,12.9
VIN+ on BOTTOM: 7.84,16.62 7.84,15.32 5.42,15.32 4.06,13.97 4.06,13.34 3.63,12.9 2.53,12.9 2.53,17.37 1.14,18.76 1.14,19.94 1.78,20.57 2.92,20.57 3.81,19.68 3.81,17.02 4.21,16.62
VIN+ on L3: 7.89,1.7 5.92,1.7 5.71,1.91 5.71,2.79 5.97,3.05 7.87,3.05 8.1,2.83 8.1,1.91
VIN+ on L3: 2.33,17.58 1.14,18.76 1.14,19.94 1.78,20.57 2.92,20.57 3.81,19.68 3.81,13.37 3.34,12.9 2.98,12.9 2.33,13.56
VIN_IC_1 on TOP: 11.94,5.46 9.65,5.46 9.65,5.97 9.27,5.97 9.27,5.97 8.76,5.97 8.76,10.85 7.78,10.85 7.78,10.24 8.26,10.24 8.26,3.63 8.9,3.63 8.9,2.49 9.89,2.49 9.89,4.3 12.05,4.3 12.57,4.83 12.87,4.83 12.87,5.68 11.94,5.68
VIN_IC_2 on TOP: 20.13,4.97 23.01,4.97 23.3,5.27 23.3,6.54 22.1,6.54 22.1,6.1 21.46,6.1 20.54,5.18 20.13,5.18
VIN_IC_2 on TOP: 24.89,2.27 26.42,2.27 26.42,3.68 24.89,3.68
VIN_IC_2 on TOP: 28.09,8.47 28.09,7.49 29.36,7.49 29.36,8.47
VIN_IC_2 on L3: 22.48,5.71 22.61,5.71 22.73,5.84 22.73,6.73 22.35,7.11 21.97,7.11 21.84,6.99 21.84,6.35
_N2 on BOTTOM: 9.17,2.97 11.22,2.97 11.22,5.26 9.17,5.26
_N3 on BOTTOM: 0.51,6.94 6.9,6.94 6.9,3.16 4.53,3.16 4.53,5.59 0.51,5.59
_N21 on TOP: 6.65,1.45 9.89,1.45 9.89,0.51 6.65,0.51
_N27 on TOP: 5.4,12.63 5.4,10.11 4.9,10.11 4.7,9.91 4.7,9.83 3.56,9.83 3.56,8.38 3.15,8.38 3.15,6.6 0.69,6.6 0.69,11.34 3.48,11.34 3.48,12.63
_N33 on TOP: 25.43,13.3 25.43,13.21 26.58,13.21 26.58,19.38 24.68,19.38 24.68,13.21 25.33,13.21 25.33,13.3
_N52 on BOTTOM: 28.87,5.72 28.87,4.7 27.69,4.7 27.69,5.72
_N83 on L2 (solid shape): outline of 202 points within 5.38,11.47 25.71,20.08
_N83 on L6 (solid shape): 25.22,20.08 25.49,19.97 25.6,19.7 25.6,11.85 25.49,11.58 25.22,11.47 7.42,11.47 7.16,11.58 7.04,11.85 7.04,15.5 7.3,16.37 8,16.95 8,18.43 8.11,18.7 8.38,18.81 24.38,18.81 24.64,18.7 24.75,18.43 24.75,13.12 24.64,12.85 24.38,12.74 8.38,12.74 8.11,12.85 8,13.12 8,15.5 8.11,15.77 8.38,15.88 8.85,15.88 8.96,15.84 9,15.73 9,14.13 9.11,13.86 9.38,13.75 23.62,13.75 23.89,13.86 24,14.13 24,17.42 23.89,17.69 23.62,17.8 9.38,17.8 9.11,17.69 9,17.42 9,16.23 8.96,16.12 8.85,16.08 8.39,16.08 7.97,15.91 7.8,15.5 7.8,13.12 7.97,12.71 8.38,12.54 24.38,12.54 24.79,12.71 24.95,13.12 24.95,18.63 24.84,18.9 24.57,19.01 8.38,19.01 7.97,18.84 7.8,18.43 7.8,17.17 7.78,17.09 7.73,17.04 7.11,16.44 6.85,15.63 6.73,15.38 6.47,15.28 5.88,15.28 5.39,15.68 5.7,16.24 5.88,16.34 6.02,16.49 6.11,16.59 6.23,16.65 6.82,17.07 7.04,17.76 7.04,19.7 7.16,19.97 7.42,20.08
_N83 on L2: 5.66,18.44 4.98,18.44 4.98,17.78 5,17.75 5.97,17.75 6.45,18.24 6.45,18.47 5.69,18.47
_N125 on TOP: 24.68,20.45 27.56,20.45 27.56,19.56 24.68,19.56
_N133 on L7 (solid shape): outline of 202 points within 5.38,11.47 25.71,20.08
_N133 on BOTTOM: 5.71,14.1 7.37,14.1 7.87,13.59 7.87,11.04 8.76,10.15 8.76,8.15 10.79,8.15 10.79,5.89 7.49,5.89 7.49,8.27 6.96,8.8 0.51,8.8 0.51,10.03 4.57,10.03 5.08,10.54 5.08,13.46
NGATE on BOTTOM: 8.83,5.26 8.83,3.3 7.87,3.3 7.87,5.26
PRI_AUX on TOP: 6.5,7.08 5.34,7.08 5.34,8.26 6.99,8.26 6.99,10.86 7.49,10.86 7.49,9.83 8.03,9.83 8.03,7.42 6.5,7.42
SEC_AUX on TOP: 25.88,10.88 25.88,10.07 27.08,8.87 27.08,7.9 27.56,7.9 27.56,8.71 29.08,8.71 29.08,10.88
SR_D on L4 (solid shape): outline of 202 points within 7.29,11.47 27.62,20.08
SR_D on L5 (solid shape): 25.58,20.08 25.84,19.97 25.96,19.7 25.96,17.76 26.18,17.07 26.77,16.65 26.89,16.59 26.98,16.49 27.12,16.34 27.3,16.24 27.61,15.68 27.12,15.28 26.53,15.28 26.27,15.38 26.15,15.63 25.89,16.44 25.27,17.04 25.22,17.09 25.2,17.17 25.2,18.43 25.03,18.84 24.62,19.01 11.95,19.01 8.42,19.01 8.16,18.9 8.04,18.63 8.04,13.12 8.21,12.71 8.63,12.54 24.62,12.54 25.03,12.71 25.2,13.12 25.2,15.5 25.03,15.91 24.61,16.08 24.15,16.08 24.04,16.12 24,16.23 24,17.42 23.89,17.69 23.62,17.8 9.38,17.8 9.11,17.69 9,17.42 9,14.13 9.11,13.86 9.38,13.75 23.62,13.75 23.89,13.86 24,14.13 24,15.73 24.04,15.84 24.15,15.88 24.62,15.88 24.89,15.77 25,15.5 25,13.12 24.89,12.85 24.62,12.74 8.63,12.74 8.36,12.85 8.24,13.12 8.24,18.43 8.36,18.7 8.62,18.81 24.62,18.81 24.89,18.7 25,18.43 25,16.95 25.7,16.37 25.96,15.5 25.96,11.85 25.84,11.58 25.58,11.47 7.78,11.47 7.51,11.58 7.4,11.85 7.4,19.7 7.51,19.97 7.78,20.08
SR_D on L8 (solid shape): outline of 244 points within 7.4,11.47 27.62,20.08
SR_D on BOTTOM: 25.91,1.4 23.55,1.4 23.55,6.26 20.9,6.26 20.9,7.59 25.91,7.59
SR_D on BOTTOM: 24.96,12.99 24.96,14.86 28.07,14.86 29.21,13.72 29.21,12.83 29.08,12.7 27.94,12.7 27.65,12.99
SR_D on L8: 29.21,12.45 29.08,12.32 29.08,8.89 26.16,5.97 26.16,2.29 25.91,2.03 24.51,2.03 24.26,2.29 24.26,6.99 28,10.73 28,12.51 27.81,12.7 27.81,13.72 28.45,13.72 28.7,13.97 29.08,13.97 29.21,13.84
VOUT on L9 (solid shape): 25.94,20.08 26.2,19.98 26.57,19.19 27.12,18.98 27.24,18.98 27.51,18.86 27.62,18.6 27.62,17.77 27.47,17.42 27.12,17.27 26.54,17.27 26.27,17.39 26.16,17.66 26.16,17.93 25.84,18.69 25.08,19.01 8.63,19.01 8.21,18.84 8.04,18.43 8.04,13.12 8.21,12.71 8.63,12.54 24.62,12.54 25.03,12.71 25.2,13.12 25.2,17.22 25.03,17.63 24.62,17.8 9.38,17.8 9.11,17.69 9,17.42 9,14.13 9.11,13.86 9.38,13.75 23.62,13.75 23.89,13.86 24,14.13 24,17.45 24.04,17.56 24.15,17.6 24.62,17.6 24.89,17.49 25,17.22 25,13.12 24.89,12.85 24.62,12.74 8.63,12.74 8.36,12.85 8.24,13.12 8.24,18.43 8.36,18.7 8.63,18.81 25.08,18.81 25.7,18.55 25.96,17.93 25.96,11.85 25.84,11.58 25.58,11.47 7.67,11.47 7.4,11.58 7.29,11.85 7.29,19.7 7.4,19.97 7.67,20.08
VOUT on BOTTOM: 26.24,17.27 31.62,17.27 31.62,20.03 26.24,20.03

Small or netless copper shapes (teardrops, artwork), in the pictures only: 1 on L3, 1 on L4, 1 on L7, 1 on L9, 1 on TOP, 1 on BOTTOM

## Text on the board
Ref Des/Silkscreen Bottom: PGND1 | ADP1074 | 08-086268a
User.Comments: XXXXXXXXXXXXXXXXX. | 4.    CORE ASSY NOTES. XXXXXXXXXXXXXXXXXXXXXXXXXXXXXXXXXXXXXXXXX
ROOT_NUMBER: CUTOUT
